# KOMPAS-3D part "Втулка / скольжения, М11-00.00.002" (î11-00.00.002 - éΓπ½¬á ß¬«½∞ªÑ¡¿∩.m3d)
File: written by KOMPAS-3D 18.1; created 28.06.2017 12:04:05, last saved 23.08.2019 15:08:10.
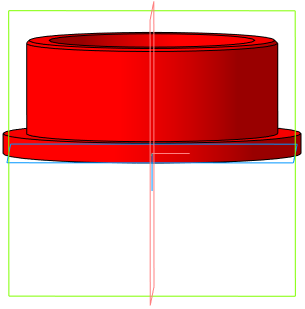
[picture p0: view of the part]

Document properties: Автор: Милов; Организация: Милов; Полное имя файла: D:\Magna\Магна Ins\Магна ins 11\Магна N\3Д\Магна INS 11\М11-00.00.002 - Втулка скольжения.m3d

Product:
- Part/product: Втулка / скольжения  | designation М11-00.00.002  | pos. 0
    Масса: 0.026501
    Раздел спецификации: Детали
    Форматы листов документа: A4
    source file: Чертежи\М11-00.00.002 - Втулка скольжения.cdw

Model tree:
1. Эскиз:1
2. Операция вращения:1
     Угол 1 = 360
3. Фаска:1  (with: Операция вращения:1)
     Угол = 45; Длина 1 = 0.5; Длина 2 = 0.5

Expressions: 20.0+1.8-2; 35.9/2; 43.9/2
